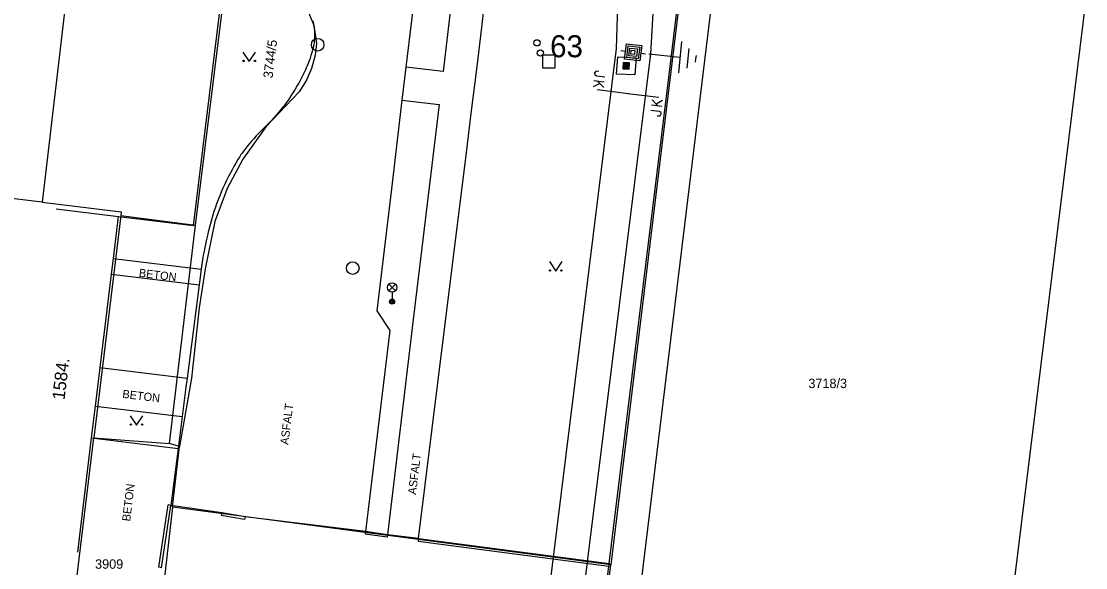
# Model space of a CAD drawing. Extents: x -540150 to -533593, y -1185082 to -1180066.
# Drawn here: x -536650.3 to -536565.8, y -1183292.5 to -1183249.1 of the extents above; entities that cross this region are included whole.
import ezdxf

# ---------------------------------------------------------------- set-up
doc = ezdxf.new("R2010")
doc.units = 0
for name, color, linetype in [('KN_HRAN_PARCEL', 7, 'Continuous'), ('KN_PARC_Č', 7, 'Continuous'), ('KN_VKP_HRAN_', 7, 'Continuous'), ('Vrstva 1', 7, 'Continuous'), ('Vrstva 10', 7, 'Continuous'), ('Vrstva 11', 7, 'Continuous'), ('Vrstva 13', 7, 'Continuous'), ('Vrstva 14', 7, 'Continuous'), ('Vrstva 15', 7, 'Continuous'), ('Vrstva 18', 7, 'Continuous'), ('Vrstva 2', 7, 'Continuous'), ('Vrstva 25', 7, 'Continuous'), ('Vrstva 26', 7, 'Continuous'), ('Vrstva 27', 7, 'Continuous'), ('Vrstva 28', 7, 'Continuous'), ('Vrstva 33', 7, 'Continuous'), ('Vrstva 36', 7, 'Continuous'), ('Vrstva 40', 7, 'Continuous'), ('Vrstva 47', 7, 'Continuous'), ('Vrstva 5', 7, 'Continuous'), ('Vrstva 7', 7, 'Continuous'), ('Vrstva 8', 7, 'Continuous')]:
    doc.layers.add(name, color=color, linetype=linetype)

# ---------------------------------------------------------------- blocks, each defined once
blk = doc.blocks.new('VN840')
at = {"layer": 'Vrstva 15'}
for points in [[(-0.009, 1.414), (-0.009, -1.086)], [(-1.092, -0.594), (-1.092, -1.243)], [(-0.678, -0.594), (-0.678, -1.421)], [(-0.678, -1.106), (-0.265, -0.594)], [(-1.505, -1.243), (-1.505, -1.145)], [(-1.476, -1.352), (-1.505, -1.243)], [(-1.328, -1.421), (-1.476, -1.352)], [(-1.269, -1.421), (-1.328, -1.421)], [(-1.131, -1.352), (-1.269, -1.421)], [(-1.092, -1.243), (-1.131, -1.352)], [(-0.541, -0.938), (-0.196, -1.421)]]:
    blk.add_lwpolyline(points, dxfattribs=at)
blk = doc.blocks.new('VN810')
at = {"layer": 'Vrstva 14'}
for points in [[(0.004, -1.247), (0.004, -3.747)], [(1.254, -3.747), (-1.246, -3.747)], [(0.772, -4.367), (-0.803, -4.367)], [(0.004, -4.997), (-0.252, -4.997)], [(0.27, -4.997), (0.004, -4.997)]]:
    blk.add_lwpolyline(points, dxfattribs=at)
blk = doc.blocks.new('VN470')
at = {"layer": 'Vrstva 2'}
for points in [[(0, 1.22), (0, 1.97)], [(-1.23, 1.22), (1.23, 1.22)], [(-1.23, -1.23), (-1.23, 1.22)], [(-0.92, 0.9), (0.92, 0.9)], [(-0.92, -0.95), (-0.92, 0.9)], [(-0.61, 0.61), (0.61, 0.61)], [(-0.61, -0.62), (-0.61, 0.61)], [(-0.31, -0.27), (-0.31, 0.34)], [(-0.31, 0.34), (0.31, 0.34)], [(0.31, 0.34), (0.31, -0.27)], [(0.61, 0.61), (0.61, -0.62)], [(0.92, 0.9), (0.92, -0.95)], [(1.23, 1.22), (1.23, -1.23)], [(1.23, -1.23), (-1.23, -1.23)], [(0.92, -0.95), (-0.92, -0.95)], [(0.61, -0.62), (-0.61, -0.62)], [(0.31, -0.27), (-0.31, -0.27)], [(0, -1.23), (0, -1.98)]]:
    blk.add_lwpolyline(points, dxfattribs=at)

msp = doc.modelspace()

# ---------------------------------------------------------------- linework, layer by layer
at = {"layer": 'KN_HRAN_PARCEL'}
for p, q in [((-536590.38, -1183184.085), (-536603.54, -1183292.265)), ((-536643.9, -1183222.715), (-536648.65, -1183263.495)), ((-536636.49, -1183265.315), (-536631.39, -1183224.205)), ((-536594.93, -1183242.705), (-536602.3, -1183303.085)), ((-536573.06, -1183306.405), (-536565.84, -1183247.595)), ((-536627.65, -1183248.115), (-536627.1, -1183249.445)), ((-536627.1, -1183249.445), (-536626.9, -1183250.905)), ((-536626.9, -1183250.905), (-536626.99, -1183251.835)), ((-536626.99, -1183251.835), (-536627.29, -1183252.885)), ((-536627.29, -1183252.885), (-536627.68, -1183253.795)), ((-536627.68, -1183253.795), (-536628.27, -1183254.725)), ((-536628.27, -1183254.725), (-536630.89, -1183257.475)), ((-536630.89, -1183257.475), (-536632.73, -1183260.065)), ((-536632.73, -1183260.065), (-536633.97, -1183262.405)), ((-536648.65, -1183263.495), (-536655.86, -1183262.625)), ((-536633.97, -1183262.405), (-536634.97, -1183265.015)), ((-536648.65, -1183263.495), (-536642.38, -1183264.255)), ((-536642.38, -1183264.255), (-536642.42, -1183264.555)), ((-536642.42, -1183264.555), (-536636.49, -1183265.315)), ((-536638.55, -1183282.645), (-536636.49, -1183265.315)), ((-536634.97, -1183265.015), (-536635.73, -1183268.785)), ((-536635.73, -1183268.785), (-536636.19, -1183271.875)), ((-536636.19, -1183271.875), (-536636.82, -1183277.465)), ((-536636.82, -1183277.465), (-536637.75, -1183282.895)), ((-536646.5, -1183298.115), (-536644.56, -1183282.195)), ((-536644.56, -1183282.195), (-536638.55, -1183282.645)), ((-536637.75, -1183282.895), (-536638.55, -1183282.645)), ((-536638.31, -1183287.695), (-536637.75, -1183282.895)), ((-536638.31, -1183287.695), (-536639.62, -1183299.015)), ((-536603.54, -1183292.265), (-536638.31, -1183287.695)), ((-536605.46, -1183307.935), (-536603.54, -1183292.265))]:
    msp.add_line(p, q, dxfattribs=at)
at = {"layer": 'KN_VKP_HRAN_'}
msp.add_line((-536642.42, -1183264.555), (-536644.56, -1183282.195), dxfattribs=at)
at = {"layer": 'Vrstva 1'}
for points in [[(-536601.309, -1183194.375), (-536603.116, -1183251.285), (-536616.536, -1183359.786)], [(-536597.1, -1183194.425), (-536600.39, -1183251.714), (-536614.104, -1183361.851)]]:
    msp.add_lwpolyline(points, dxfattribs=at)
at = {"layer": 'Vrstva 10'}
for p, q in [((-536619.8, -1183252.765), (-536620.111, -1183255.396)), ((-536620.111, -1183255.396), (-536620.945, -1183262.435)), ((-536633.453, -1183260.671), (-536633.595, -1183260.929)), ((-536620.945, -1183262.435), (-536622.09, -1183272.105)), ((-536636.05, -1183268.795), (-536636.21, -1183270.041)), ((-536636.21, -1183270.041), (-536637.162, -1183277.447)), ((-536622.09, -1183272.105), (-536621.07, -1183273.685)), ((-536621.07, -1183273.685), (-536623, -1183289.635)), ((-536637.162, -1183277.447), (-536637.256, -1183278.175))]:
    msp.add_line(p, q, dxfattribs=at)
for points in [[(-536618.923, -1183245.402), (-536619.363, -1183249.083), (-536619.8, -1183252.765)], [(-536627.192, -1183249.109), (-536627.163, -1183249.228), (-536627.138, -1183249.34), (-536627.117, -1183249.446), (-536627.1, -1183249.544), (-536627.074, -1183249.729), (-536627.057, -1183249.89), (-536627.047, -1183250.03), (-536627.041, -1183250.151), (-536627.04, -1183250.256), (-536627.04, -1183250.347), (-536627.046, -1183250.504), (-536627.054, -1183250.62), (-536627.063, -1183250.706), (-536627.079, -1183250.832), (-536627.1, -1183250.955), (-536627.128, -1183251.094), (-536627.158, -1183251.229), (-536627.189, -1183251.36), (-536627.222, -1183251.486), (-536627.256, -1183251.609), (-536627.328, -1183251.846), (-536627.402, -1183252.069), (-536627.477, -1183252.277), (-536627.552, -1183252.473), (-536627.626, -1183252.656), (-536627.7, -1183252.827)], [(-536627.7, -1183252.827), (-536627.771, -1183252.987), (-536627.841, -1183253.138), (-536627.978, -1183253.419), (-536628.104, -1183253.664), (-536628.219, -1183253.878), (-536628.322, -1183254.065), (-536628.415, -1183254.228), (-536628.583, -1183254.512), (-536628.713, -1183254.724), (-536628.914, -1183255.04), (-536629.12, -1183255.355), (-536629.236, -1183255.524), (-536629.351, -1183255.684), (-536629.464, -1183255.836), (-536629.576, -1183255.98), (-536629.686, -1183256.118), (-536629.794, -1183256.249), (-536629.901, -1183256.373), (-536630.109, -1183256.61), (-536630.308, -1183256.828), (-536630.496, -1183257.028), (-536630.851, -1183257.396), (-536631.163, -1183257.715), (-536631.434, -1183257.993), (-536631.668, -1183258.237), (-536631.87, -1183258.453), (-536632.043, -1183258.645), (-536632.192, -1183258.815), (-536632.32, -1183258.966), (-536632.43, -1183259.1), (-536632.524, -1183259.219), (-536632.685, -1183259.431), (-536632.802, -1183259.594), (-536632.887, -1183259.719), (-536633.011, -1183259.909), (-536633.13, -1183260.105), (-536633.298, -1183260.396), (-536633.453, -1183260.671)], [(-536633.595, -1183260.929), (-536633.725, -1183261.173), (-536633.845, -1183261.402), (-536633.954, -1183261.618), (-536634.055, -1183261.822), (-536634.147, -1183262.013), (-536634.314, -1183262.374), (-536634.454, -1183262.693), (-536634.572, -1183262.974), (-536634.671, -1183263.221), (-536634.755, -1183263.438), (-536634.825, -1183263.63), (-536634.943, -1183263.967), (-536635.027, -1183264.221)], [(-536635.027, -1183264.221), (-536635.086, -1183264.413), (-536635.171, -1183264.703), (-536635.25, -1183264.995), (-536635.371, -1183265.467), (-536635.475, -1183265.881), (-536635.563, -1183266.243), (-536635.637, -1183266.56), (-536635.7, -1183266.837), (-536635.752, -1183267.08), (-536635.839, -1183267.507), (-536635.9, -1183267.828), (-536635.942, -1183268.069), (-536635.999, -1183268.431), (-536636.05, -1183268.795)], [(-536637.256, -1183278.175), (-536637.557, -1183280.512), (-536637.881, -1183283.039), (-536638.462, -1183287.554)]]:
    msp.add_lwpolyline(points, dxfattribs=at)
at = {"layer": 'Vrstva 11'}
for p, q in [((-536614.908, -1183236.972), (-536616.845, -1183253.119)), ((-536613.778, -1183249.627), (-536613.036, -1183243.438)), ((-536616.845, -1183253.119), (-536619.8, -1183252.765)), ((-536620.111, -1183255.396), (-536617.16, -1183255.745)), ((-536617.16, -1183255.745), (-536619.21, -1183272.815)), ((-536617.175, -1183277.195), (-536615.56, -1183264.205)), ((-536643.001, -1183267.95), (-536636.05, -1183268.795)), ((-536643.152, -1183269.197), (-536636.21, -1183270.041)), ((-536619.21, -1183272.815), (-536621.26, -1183289.885)), ((-536644.053, -1183276.61), (-536637.162, -1183277.447)), ((-536618.79, -1183290.185), (-536617.175, -1183277.195)), ((-536644.426, -1183279.677), (-536637.557, -1183280.512)), ((-536644.734, -1183282.206), (-536637.881, -1183283.039))]:
    msp.add_line(p, q, dxfattribs=at)
for points in [[(-536614.605, -1183256.447), (-536614.177, -1183252.927), (-536613.778, -1183249.627)], [(-536615.56, -1183264.205), (-536615.065, -1183260.201), (-536614.605, -1183256.447)]]:
    msp.add_lwpolyline(points, dxfattribs=at)
at = {"layer": 'Vrstva 25'}
for points in [[(-536602.571, -1183252.908), (-536602.072, -1183252.941), (-536602.039, -1183252.442), (-536602.538, -1183252.409)], [(-536602.518, -1183252.861), (-536602.119, -1183252.888), (-536602.092, -1183252.489), (-536602.491, -1183252.462)], [(-536602.465, -1183252.815), (-536602.166, -1183252.835), (-536602.145, -1183252.535), (-536602.445, -1183252.515)], [(-536602.412, -1183252.768), (-536602.212, -1183252.781), (-536602.199, -1183252.582), (-536602.398, -1183252.568)], [(-536602.358, -1183252.721), (-536602.259, -1183252.728), (-536602.252, -1183252.628), (-536602.352, -1183252.622)]]:
    msp.add_lwpolyline(points, close=True, dxfattribs=at)
at = {"layer": 'Vrstva 26'}
msp.add_lwpolyline([(-536608.95, -1183252.825), (-536607.95, -1183252.825), (-536607.95, -1183251.825), (-536608.95, -1183251.825)], close=True, dxfattribs=at)
at = {"layer": 'Vrstva 27'}
for centre in [(-536626.795, -1183250.992), (-536624.01, -1183268.725)]:
    msp.add_circle(centre, 0.5, dxfattribs=at)
at = {"layer": 'Vrstva 28'}
for centre in [(-536609.39, -1183250.845), (-536609.12, -1183251.655)]:
    msp.add_circle(centre, 0.25, dxfattribs=at)
at = {"layer": 'Vrstva 33'}
for p, q in [((-536621.155, -1183270.525), (-536620.625, -1183269.995)), ((-536621.155, -1183269.995), (-536620.625, -1183270.525)), ((-536620.89, -1183270.635), (-536620.89, -1183271.385))]:
    msp.add_line(p, q, dxfattribs=at)
for centre, radius in [((-536620.89, -1183270.26), 0.375), ((-536620.89, -1183271.385), 0.2), ((-536620.89, -1183271.385), 0.145), ((-536620.89, -1183271.385), 0.0876)]:
    msp.add_circle(centre, radius, dxfattribs=at)
at = {"layer": 'Vrstva 36'}
for points in [[(-536632.726, -1183251.579), (-536632.226, -1183252.329), (-536631.726, -1183251.579)], [(-536608.405, -1183268.211), (-536607.905, -1183268.961), (-536607.405, -1183268.211)], [(-536641.678, -1183280.445), (-536641.178, -1183281.195), (-536640.678, -1183280.445)]]:
    msp.add_lwpolyline(points, dxfattribs=at)
for centre in [(-536632.676, -1183252.279), (-536631.777, -1183252.279), (-536608.355, -1183268.911), (-536607.456, -1183268.911), (-536641.628, -1183281.145), (-536640.729, -1183281.145)]:
    msp.add_circle(centre, 0.05, dxfattribs=at)
at = {"layer": 'Vrstva 5'}
for p, q in [((-536636.64, -1183265.345), (-536631.69, -1183224.625)), ((-536647.559, -1183264.017), (-536642.596, -1183264.621)), ((-536643.001, -1183267.95), (-536642.596, -1183264.621)), ((-536642.596, -1183264.621), (-536636.64, -1183265.345)), ((-536643.152, -1183269.197), (-536643.001, -1183267.95)), ((-536644.053, -1183276.61), (-536643.152, -1183269.197)), ((-536644.426, -1183279.677), (-536644.053, -1183276.61)), ((-536644.734, -1183282.206), (-536644.426, -1183279.677)), ((-536645.835, -1183291.267), (-536644.734, -1183282.206))]:
    msp.add_line(p, q, dxfattribs=at)
at = {"layer": 'Vrstva 7'}
for p, q in [((-536598.92, -1183253.585), (-536593.01, -1183203.855)), ((-536603.67, -1183292.175), (-536598.92, -1183253.585)), ((-536639.195, -1183292.5), (-536638.462, -1183287.554)), ((-536638.462, -1183287.554), (-536638.66, -1183287.525)), ((-536634.41, -1183288.155), (-536634.444, -1183288.352)), ((-536632.56, -1183288.475), (-536634.41, -1183288.155)), ((-536632.594, -1183288.672), (-536634.444, -1183288.352)), ((-536632.56, -1183288.475), (-536632.594, -1183288.672)), ((-536623, -1183289.635), (-536623.028, -1183289.833)), ((-536621.288, -1183290.083), (-536623.028, -1183289.833)), ((-536621.26, -1183289.885), (-536623, -1183289.635)), ((-536621.26, -1183289.885), (-536621.288, -1183290.083)), ((-536618.79, -1183290.185), (-536618.816, -1183290.383)), ((-536618.816, -1183290.383), (-536603.694, -1183292.373)), ((-536606.71, -1183317.885), (-536603.694, -1183292.373))]:
    msp.add_line(p, q, dxfattribs=at)
for points in [[(-536603.08, -1183253.325), (-536602.98, -1183251.955), (-536601.53, -1183252.025), (-536601.63, -1183253.395), (-536603.08, -1183253.325)], [(-536639.195, -1183292.5), (-536639.393, -1183292.471), (-536638.66, -1183287.525)], [(-536618.79, -1183290.185), (-536603.67, -1183292.175), (-536603.694, -1183292.373)]]:
    msp.add_lwpolyline(points, dxfattribs=at)
at = {"layer": 'Vrstva 8'}
for p, q in [((-536634.41, -1183288.155), (-536638.462, -1183287.554)), ((-536623, -1183289.635), (-536632.56, -1183288.475)), ((-536618.79, -1183290.185), (-536621.26, -1183289.885))]:
    msp.add_line(p, q, dxfattribs=at)

# ---------------------------------------------------------------- block references
at = {"layer": 'Vrstva 13', "xscale": 0.49999999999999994, "yscale": 0.49999999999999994, "rotation": 82.98433892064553}
msp.add_blockref('VN470', (-536601.767, -1183251.597), dxfattribs=at)
at = {"layer": 'Vrstva 15', "rotation": 83.96296944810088}
msp.add_blockref('VN810', (-536601.767, -1183251.595), dxfattribs=at)
at = {"layer": 'Vrstva 18'}
for p, rotation in [((-536603.54, -1183254.714), -97.0508000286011), ((-536600.802, -1183255.023), 82.90211393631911)]:
    msp.add_blockref('VN840', p, dxfattribs=dict(at, rotation=rotation))

# ---------------------------------------------------------------- texts
at = {"layer": 'KN_PARC_Č'}
msp.add_text('3744/5', height=0.75, rotation=83, dxfattribs=at).set_placement((-536630.377, -1183253.688))
for s, p in [('3718/3', (-536587.85, -1183278.245)), ('3909', (-536644.46, -1183292.585))]:
    msp.add_text(s, height=0.75, dxfattribs=at).set_placement(p)
at = {"layer": 'Vrstva 14'}
msp.add_text('63', height=1.75, dxfattribs=at).set_placement((-536608.349, -1183251.988))
at = {"layer": 'Vrstva 40'}
for s, rotation, p in [('BETON', 353.06807, (-536641.017, -1183269.409)), ('BETON', 353.06909, (-536642.324, -1183279.018)), ('ASFALT', 83.10058, (-536629.126, -1183282.774)), ('ASFALT', 82.91299, (-536618.997, -1183286.728)), ('BETON', 83.06932, (-536641.681, -1183288.85))]:
    msp.add_text(s, height=0.65, rotation=rotation, dxfattribs=at).set_placement(p)
at = {"layer": 'Vrstva 47'}
msp.add_text('1584.', height=1, rotation=83.06932, dxfattribs=at).set_placement((-536646.89, -1183279.22))

doc.saveas('drawing.dxf')
